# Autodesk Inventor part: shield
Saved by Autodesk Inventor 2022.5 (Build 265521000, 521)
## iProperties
Created: 2024-12
Part Number: shield
Material: Generic
Document SubType Name: Modeling
Designer: AdminForWorker
Density: 1 g/cm^3
Appearance: Default
Title: shield
Author: AdminForWorker
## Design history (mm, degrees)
feature "Body1"
body "Solid1"
